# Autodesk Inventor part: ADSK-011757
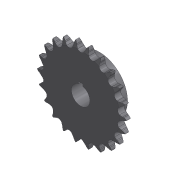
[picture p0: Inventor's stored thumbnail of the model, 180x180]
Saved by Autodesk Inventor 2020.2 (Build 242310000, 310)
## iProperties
Created: 1999-12
Part Number: ADSK-011757
Material: Acier (alliage faible hypertrempé)
Description: SPROCKET,B,50B22,1.00B,0.25 KEY
Document SubType Name: Modeling
Designer: gpurviance
Density: 7.84 g/cm^3
Appearance: Metal-Steel(Polish)
Mass: 1115.15 g
Surface Area: 279.325 cm^2
Volume: 142.239 cm^3
Control State: 0
Master: False
Checked Out: False
Shininess: 0.0
Length Units: 11269
Angle Units: 11279
Time Units: 11290
Mass Units: 11283
Length Display Precision: 3
Angle Display Precision: 2
Compacted: True
Material Desc: SPROCKET,B,40B
Material_number: A08xxxx
Dimensions: 120,4x25,4x121,6 mm
Mass: 1,115 kg
VLT_Material: Acier (alliage faible hypertrempé)
Density: 0.0
Volumn: 0.0
Area: 0.0
PropertySet Name: Model Information
Author: gpurviance
Revision Number: -
Title: SPROCKET,B,50B22,1.00B,0.25 KEY
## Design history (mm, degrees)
node "Solide1"
node "Corps solides"
node "Corps surfaciques"
node "Sprocket blank" dims "d1" = 8.7122 (= thk), "d2" = 0
node "Half of tooth shape" dims "d15" = 8.7122 (= thk), "d16" = 0
node "Sprocket centerline"
node "Hub" dims "d28" = 16.6878 (= hubthk), "d29" = 0
node "Bore extrusion" dims "d31" = 16.6878 (= hubthk), "d32" = 0 (computed from Taper)
node "Mirror of tooth half"
node "tooth array" dims "d17" = 220 (= N_1), "d19" = 2.85599 (computed from N_1)
node "Revolution2" dims "d46" = 90 deg
node "Extrusion6" dims "d51" = 25.4, "d52" = 0
workplane "Arbeitsebene1"
sketch "Sketch1"
  geometry: C1 r 50.694 at (0, 0)
  constraints: 1 centre point
  dimensions: "d0" = 50.69423 radius of C1 (computed from N_1, Pitch, Dr)
sketch "Sketch2" dims "d5" = 10.16 (= Dr)
  geometry: L1 (0, 60.833)-(0, 0); L2 (0, 0)-(17.139, 58.369); L3 (0, 0)-(8.657, 60.214); L4 (0, 55.774)-(-7.642, 55.774); L5 (4.018, 52.666)-(-6.429, 60.748); L6 (-6.429, 60.748)-(14.048, 52.361); L7 (-4.776, 61.473)-(17.347, 52.411); L8 (5.794, 55.742)-(6.285, 56.942); L9 (19.508, 67.172)-(14.02, 53.774); L10 (8.653, 60.181)-(7.215, 50.178); C1 r 50.694 at (0, 0) reference; C2 r 43.904 at (0, 0); A1 r 5.08 centre (0, 55.774) between (0, 50.694) and (4.018, 52.666); A2 r 13.208 centre (-6.429, 60.748) between (4.018, 52.666) and (5.794, 55.742); A3 r 8.359 centre (14.02, 53.774) between (8.653, 60.181) and (6.285, 56.942); A4 r 50.694 centre (0, 0) between (7.215, 50.178) and (0, 50.694)
  constraints: 20 end point, 8 point on circle, 5 centre point, 5 point on line, 4 coincident, 2 equal length, 2 tangent, 1 collinear, 1 horizontal, 1 midpoint, 1 parallel, 1 vertical, 1 vertical alignment, 3 other
  dimensions: "d7" = 8.18182 deg angle of L3 L1 (computed from N_1); "d8" = 8.18182 deg angle of L2 L3 (= d7); "d9" = 37.7273 deg angle of L5 L4 (computed from N_1); "d10" = 15.4545 deg angle of L6 L5 (computed from N_1); "d11" = 8.128 distance of L4.start L5.end (= 0.8 x Dr); "d12" = 1.29709 distance between parallel lines of L6 L7 (computed from Dr, N_1); "d13" = 60.83307 distance of L1.end L2.end (= 1.2 x d0); "d14" = 8.35862 distance between parallel lines of L9 L8 (computed from N_1, Dr); "d33" = 50.69423 radius of A4 (= d0); "d48" = 87.8078 diameter of C2
sketch "Sketch5"
  geometry: C1 r 50.694 at (0, 0) reference; C2 r 38.1 at (0, 0)
  constraints: 1 centre point, 1 coincident
  dimensions: "d27" = 76.2 diameter of C2 (= hubdia)
sketch "Sketch6"
  geometry: C1 r 38.1 at (0, 0) reference; C2 r 12.5 at (0, 0)
  constraints: 1 centre point, 1 coincident
  dimensions: "d30" = 25 diameter of C2 (= bore)
sketch "Sketch7"
  geometry: L1 (8.712, -10.106)-(8.712, 0) reference; L2 (0, 0)-(8.712, 0) reference; L3 (0, -10.106)-(0, 0) reference; L4 (1.984, 0)-(0, -7.938); L5 (6.728, 0)-(8.712, -7.938); L6 (0, 0)-(-4.356, 0); L7 (-4.356, 0)-(-4.356, -16.65); L8 (-4.356, -16.65)-(0, -16.65); L9 (0, -16.65)-(0, 0); L10 (-6.97, -60.8)-(11.326, -60.8) reference
  constraints: 12 end point, 4 point on line, 2 parallel, 1 horizontal, 1 perpendicular
  dimensions: "d40" = 1.98374 distance from line of L4.start L3 (= G); "d41" = 1.98374 distance from line of L5.start L1 (= G); "d42" = 7.9375 distance from line of L5.end L2 (= h); "d43" = 7.9375 distance from line of L4.end L2 (= h); "d44" = 8.7122 distance from line of L8 L5.end (= thk); "d45" = 4.3561 distance between parallel lines of L3 L7 (= 0.5 x thk)
sketch "Sketch8"
  geometry: L1 (-3, 15)-(3, 15); L2 (0, 0)-(0, 15); L3 (-3, 15)-(-3, 12.135); L4 (3, 15)-(3, 12.135); C1 r 38.1 at (0, 0) reference; A1 r 12.5 centre (0, 0) between (-3, 12.135) and (3, 12.135) reference
  constraints: 8 end point, 2 parallel, 2 point on circle, 1 horizontal, 1 midpoint, 1 perpendicular
  dimensions: "d49" = 6 distance of L1.start L1.end; "d50" = 15 distance of L2.start L2.end
other parameters: "Pitch" = 15.875 [user parameter; used in 1 equation term], "Dr" = 10.16 [user parameter; used in 5 equation terms], "thk" = 8.7122 [user parameter; used in 5 equation terms], "h" = 7.9375 [user parameter; used in 2 equation terms], "G" = 1.98374 [user parameter; used in 2 equation terms], "hubdia" = 76.2 [user parameter; used in 1 equation term], "hubthk" = 16.6878 (computed from thk) [user parameter; used in 2 equation terms], "bore" = 25 [user parameter; used in 1 equation term], "Taper" = 0 [user parameter; used in 1 equation term]
